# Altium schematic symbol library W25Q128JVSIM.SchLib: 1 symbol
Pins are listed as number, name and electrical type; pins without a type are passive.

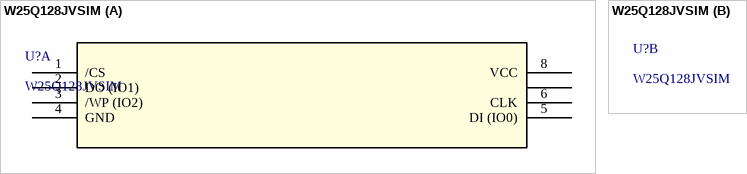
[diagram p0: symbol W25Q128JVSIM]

## W25Q128JVSIM
designator U?
Description; Manufacturer_Name: Winbond
footprint SOIC_128JVSIM_WIN
part A pins: 1 /CS, 2 DO (IO1), 3 /WP (IO2), 4 GND (power), 5 DI (IO0), 6 CLK, 8 VCC (power), ?1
